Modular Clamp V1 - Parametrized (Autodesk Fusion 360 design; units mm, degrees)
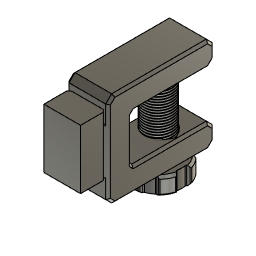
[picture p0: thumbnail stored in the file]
parameter "Thread_Diameter" = 25
parameter "Bolt_Head_Diameter" = 45
parameter "Bolt_Head_Height" = 15
parameter "Clamp_Clearance" = 40
parameter "Clamp_Strenght" = 20
parameter "Clamp_Length" = 70
parameter "Clamp_Thread_Clearance" = 10
parameter "Bolt_Length" = 60 (= "Clamp_Clearance + Clamp_Strenght")
parameter "Thread_Back_Offset" = 30 (= "Clamp_Strenght * 1.5")
parameter "Clamp_Width" = 35 (= "Thread_Diameter + Clamp_Strenght / 2")
parameter "Chamfer_Small" = 2 (= "Clamp_Strenght / 10")
parameter "Chamfer_Large" = 5 (= "Clamp_Strenght / 4")
parameter "Bolt_Chamfer" = 3.125 (= "Thread_Diameter / 8")
parameter "Thread_Tolerance_Additional" = 0.3
parameter "Knurling_Depth" = 3 (= "Bolt_Head_Diameter / 15")
parameter "Knurling_Angle" = 40
parameter "Mount_Strength" = 30
parameter "Mount_Height" = 40 (= "Clamp_Clearance")
parameter "Slot_Undercut" = 8
parameter "Slot_Height" = 20
parameter "Slot_Width" = 30
parameter "Mount_Chamfer_Tolerance" = 1
parameter "Slot_Tolerance" = 0.3
parameter "d157" = 15.5 (= "( Clamp_Width - Chamfer_Small * 2 ) / 2")
sketch "Clamp Side" plane through (0, 0, 0) normal (1, 0, 0) x axis (0, 1, 0)
  line L1 (-35, -20) -> (35, -20)
  line L2 (-35, 20) -> (-35, -20)
  line L3 (35, 20) -> (-35, 20)
  line L4 (35, -20) -> (35, 20)
  line L5 (-35, 20) -> (35, -20)
  line L6 (35, 20) -> (-35, -20)
  line L7 (-55, -40) -> (55, -40)
  line L8 (-55, 40) -> (-55, -40)
  line L9 (55, 40) -> (-55, 40)
  line L10 (55, -40) -> (55, 40)
  line L11 (49.6989, -40) -> (49.6989, 40)
  line L12 (-35, -60) -> (35, -60)
  line L13 (-35, 60) -> (-35, -60)
  line L14 (35, 60) -> (-35, 60)
  line L15 (35, -60) -> (35, 60)
  line L16 (-35, 60) -> (35, -60)
  line L17 (35, 60) -> (-35, -60)
  point P6 (0, 0)
  point P1 (0, 0)
  point P11 (49.6989, 40)
  point P12 (49.6989, -40)
  point P17 (0, 0)
  point P4 (-35, 20)
  point P5 (35, 20)
  point P3 (-35, -20)
  point P15 (-35, 60)
  point P16 (35, 60)
  point P14 (-35, -60)
  horizontal L1
  perpendicular L1 L2
  parallel L1 L3
  parallel L2 L4
  coincident L5 P6
  coincident L6 P6
  coincident P1 P6
  coincident L9 P11
  coincident L7 P12
  perpendicular L7 L11
  horizontal L12
  perpendicular L12 L13
  parallel L12 L14
  parallel L13 L15
  coincident L16 P17
  coincident L17 P17
  coincident P1 P17
  dimension "d8" distance P4 P5 = 70 (= "Clamp_Length")
  dimension "d9" distance P3 P4 = 40 (= "Clamp_Clearance")
  dimension "d21" distance P15 P16 = 70 (= "Clamp_Length")
  dimension "d22" distance P14 P15 = 120 (= "Bolt_Length + Clamp_Strenght * 3")
extrude "Extrude1" new body sketch "Clamp Side" profile of L1 L2 L3 L8 L7 L9 L12 L13 L14 L15 distance 17.5 (= "Clamp_Width / 2")
sketch "Thread and Bolt" plane through (0, 0, -40) normal (0, 0, -1) x axis (1, 0, 0)
  line L1 (17.5, 55) -> (17.5, -35)
  line L2 (-17.5, 55) -> (17.5, 55)
  line L3 (-17.5, -35) -> (-17.5, 55)
  line L4 (17.5, -35) -> (-17.5, -35)
  line L5 (19.5, -5) -> (22.5, -5)
  line L6 (19.0853, -1) -> (19.5, -5)
  line L7 (21.644, 1.147) -> (19.0853, -1)
  line L8 (15.0111, -5) -> (11.2583, 1.5)
  line L9 (19.5, -5) -> (0, -5)
  line L10 (11.2583, -5) -> (0, -5)
  line L11 (1.5, 1.5) -> (11.2583, 1.5)
  line L12 (1.5, -5) -> (1.5, 1.5)
  line L13 (11.2583, -5) -> (1.5, -5)
  line L14 (11.2583, 1.5) -> (11.2583, -5)
  line L15 (15.0111, -5) -> (11.2583, -11.5)
  line L16 (11.2583, -11.5) -> (11.2583, -5)
  line L17 (1.5, -11.5) -> (11.2583, -11.5)
  line L18 (1.5, -5) -> (1.5, -11.5)
  line L19 (5.9587, 43.003) -> (-11.5413, 43.003)
  line L20 (5.9587, 38.003) -> (5.9587, 43.003)
  line L21 (-11.5413, 38.003) -> (5.9587, 38.003)
  line L22 (-12.0413, 42.503) -> (-12.0413, 38.503)
  line L23 (2.4946, 35.3691) -> (2.4946, 45.637)
  line L24 (12.1369, 40.07) -> (3.2446, 34.936)
  line L25 (3.2446, 46.07) -> (12.1369, 40.936)
  circle C1 centre (0, -5) radius 12.5
  circle C2 centre (0, -5) radius 22.5
  circle C3 centre (0, -5) radius 9.375
  circle C4 centre (0, -5) radius 19.5
  circle C5 centre (0, -5) radius 13
  arc A1 centre (2.9946, 45.637) radius 0.5 clockwise from (2.4946, 45.637) to (3.2446, 46.07)
  arc A2 centre (11.8869, 40.503) radius 0.5 clockwise from (12.1369, 40.936) to (12.1369, 40.07)
  arc A3 centre (2.9946, 35.3691) radius 0.5 clockwise from (3.2446, 34.936) to (2.4946, 35.3691)
  arc A4 centre (-11.5413, 42.503) radius 0.5 clockwise from (-12.0413, 42.503) to (-11.5413, 43.003)
  arc A5 centre (-11.5413, 38.503) radius 0.5 clockwise from (-11.5413, 38.003) to (-12.0413, 38.503)
  point P6 (0, -5)
  point P7 (0, -5)
  point P11 (22.5, -5)
  point P12 (19.5, -5)
  point P13 (19.0853, -1)
  point P14 (21.644, 1.147)
  point P8 (0, -5)
  point P16 (0, -5)
  point P15 (15.0111, -5)
  point P17 (0, -5)
  point P20 (11.2583, 1.5)
  point P21 (11.2583, 1.5)
  point P26 (15.0111, -5)
  point P25 (11.2583, -11.5)
  point P28 (11.2583, -11.5)
  point P22 (1.5, 1.5)
  point P29 (1.5, -11.5)
  point P23 (1.5, -5)
  point P30 (1.5, -5)
  point P24 (11.2583, -5)
  point P27 (11.2583, -5)
  point P35 (5.9587, 40.503)
  point P33 (2.4946, 46.503)
  point P34 (2.4946, 34.503)
  point P9 (0, -5)
  coincident P6 P7
  concentric C1 C2
  concentric C2 C3
  coincident C2 P11
  coincident C4 P12
  perpendicular L1 L5
  coincident C4 P13
  coincident C2 P14
  coincident P8 L5
  coincident P8 P16
  coincident P15 L9
  horizontal L10
  coincident P6 P17
  tangent L8 C5
  horizontal L11
  vertical L12
  horizontal L13
  vertical L14
  collinear L9 L13
  coincident P20 P21
  symmetric P15 L9 P26
  symmetric L9 P20 P25
  symmetric L9 P21 P28
  symmetric L9 P22 P29
  symmetric L9 P23 P30
  symmetric L9 P24 P27
  horizontal L19
  vertical L20
  horizontal L21
  vertical L22
  parallel L22 L23
  midpoint L20 P35
  coincident P33 L23
  coincident P33 L25
  tangent L23 A1
  tangent L25 A1
  tangent L24 A2
  tangent L25 A2
  equal A1 A2
  coincident P34 L23
  coincident P34 L24
  tangent L23 A3
  tangent L24 A3
  equal A1 A3
  tangent L19 A4
  tangent L22 A4
  equal A1 A4
  tangent L21 A5
  tangent L22 A5
  equal A1 A5
  dimension "d17" diameter C1 = 25 (= "Thread_Diameter")
  dimension "d23" distance P7 L4 = 30 (= "Thread_Back_Offset")
  dimension "d26" diameter C2 = 45 (= "Bolt_Head_Diameter")
  dimension "d48" diameter C3 = 18.75 (= "Thread_Diameter - Bolt_Chamfer * 2")
  dimension "d55" distance L3 P9 = 17.5 (= "Clamp_Width / 2")
  dimension "d58" angle L5 L7 = 40 (= "Knurling_Angle")
  dimension "d73" angle L8 L9 = 60
  dimension "d80" = 0.5
  dimension "d81" distance P33 P34 = 12
  dimension "d82" radius A1 = 0.5
  dimension "d83" distance L19 L21 = 5
  dimension "d84" distance P33 P35 = 6 (= "d81 / 2")
  dimension "d182" distance P12 P13 = 4
extrude "Extrude2" cut sketch "Thread and Bolt" profile of C1 C3 to an object
thread "Thread1"
extrude "Extrude3" new body sketch "Thread and Bolt" profile of L1 L3 C1 C2 along normal blind 15 (= "Bolt_Head_Height") bodies "Bolt 60 mm"
extrude "Extrude4" new body sketch "Thread and Bolt" profile of C1 no distance stored
combine "Combine1"
chamfer "Chamfer3" distance 2 (= "Chamfer_Small")
thread "Thread2"
offset_faces "OffsetFaces4"
offset_faces "OffsetFaces5"
extrude "Extrude5" new body sketch "Thread and Bolt" profile of C1 C3 no distance stored
chamfer "Chamfer4" distance 3.125 (= "Bolt_Chamfer")
combine "Combine2"
chamfer "Chamfer5" distance 5 (= "Chamfer_Large")
chamfer "Chamfer6" distance 2 (= "Chamfer_Small")
chamfer "Chamfer7" distance 2 (= "Chamfer_Small")
extrude "Extrude6" cut sketch "Thread and Bolt" profile of L1 C2 C4 L5 L7 along normal blind 15 (= "Bolt_Head_Height")
mirror "Mirror1" mirrorStitchTolerance 0.1
fillet "Fillet2" radius 1 (= "Knurling_Depth / 3")
circular_pattern "C-Pattern2" TotalAngle 360
extrude "Extrude7" cut sketch "Thread and Bolt" profile of C1 C3 L8 L9 L10 C5 L11 L13 L14 L15 L16 L17 to an object
sketch "Mount Base" plane through (0, 0, 0) normal (0, 1, 0) x axis (1, 0, 0)
  line L1 (-15.5, 20) -> (15.5, 20)
  line L2 (-15.5, -20) -> (-15.5, 20)
  line L3 (15.5, -20) -> (-15.5, -20)
  line L4 (15.5, 20) -> (15.5, -20)
  line L5 (-15.5, -20) -> (15.5, 20)
  line L6 (15.5, -20) -> (-15.5, 20)
  point P6 (0, 0)
  point P1 (0, 0)
  point P4 (-15.5, -20)
  point P5 (15.5, -20)
  point P3 (-15.5, 20)
  horizontal L1
  perpendicular L1 L2
  parallel L1 L3
  parallel L2 L4
  coincident L5 P6
  coincident L6 P6
  coincident P1 P6
  dimension "d107" distance P4 P5 = 31
  dimension "d108" distance P3 P4 = 40
extrude "Extrude12" sketch "Mount Base" profile of L1 L2 L3 L4 no distance stored
sketch "Mount Profile" plane through (0, 0, -20) normal (0, 0, -1) x axis (1, 0, 0)
  line L1 (0, -22.5) -> (0, -1.75)
  line L2 (15.5, 55) -> (-15.5, 55)
  line L3 (15.5, 85) -> (15.5, 55)
  line L4 (-15.5, 85) -> (15.5, 85)
  line L5 (-15.5, 55) -> (-15.5, 85)
  line L6 (0, 55) -> (0, 85)
  line L7 (-2.1213, 68.3787) -> (-15.5, 55)
  line L8 (5.3866, 55) -> (-15.5, 55)
  line L9 (15.5, 55) -> (2.1213, 68.3787)
  line L10 (15.5, 55) -> (-15.5, 55)
  line L11 (-2.1213, 62.7218) -> (-9.8431, 55)
  line L12 (9.8431, 55) -> (2.1213, 62.7218)
  line L13 (-1.9092, 62.5097) -> (-9.631, 54.7879)
  line L14 (9.631, 54.7879) -> (1.9092, 62.5097)
  line L15 (15.5, 55) -> (-15.5, 55)
  line L16 (15.5, 76.2574) -> (15.5, 55)
  line L17 (-15.5, 76.2574) -> (15.5, 76.2574)
  line L18 (-15.5, 55) -> (-15.5, 76.2574)
  line L19 (12.6716, 52.1716) -> (9.8431, 55)
  line L20 (-12.6716, 52.1716) -> (12.6716, 52.1716)
  line L21 (-9.8431, 55) -> (-12.6716, 52.1716)
  line L22 (17.5, 53) -> (17.5, 49.1716)
  line L23 (15.5, 55) -> (12.6716, 52.1716)
  arc A1 centre (0, 66.2574) radius 3 clockwise from (-2.1213, 68.3787) to (2.1213, 68.3787)
  arc A2 centre (0, 60.6005) radius 3 clockwise from (-2.1213, 62.7218) to (2.1213, 62.7218)
  arc A3 centre (0, 60.6005) radius 2.7 clockwise from (-1.9092, 62.5097) to (1.9092, 62.5097)
  point P8 (0, 85)
  point P9 (0, 55)
  point P4 (-15.5, 55)
  point P10 (-15.5, 55)
  point P5 (15.5, 55)
  point P12 (15.5, 55)
  point P13 (-9.8431, 55)
  point P14 (9.8431, 55)
  point P28 (15.5, 76.2574)
  point P26 (-15.5, 55)
  point P17 (0, 66.2574)
  point P34 (15.5, 55)
  midpoint L4 P8
  midpoint L2 P9
  horizontal L8
  coincident P4 P10
  coincident P5 P12
  coincident L8 P13
  parallel L7 L11
  coincident L2 P14
  parallel L9 L12
  tangent L7 A1
  tangent L9 A1
  tangent L12 A2
  tangent L11 A2
  equal A1 A2
  horizontal L15
  vertical L16
  horizontal L17
  vertical L18
  coincident L3 P28
  coincident P4 P26
  parallel L9 L19
  parallel L15 L20
  parallel L11 L21
  coincident L6 P17
  coincident P5 P34
  dimension "d159" angle L7 L8 = 45
  dimension "d160" distance L7 L11 = 4
  dimension "d162" radius A1 = 3
  dimension "d166" distance P17 L17 = 10
  dimension "d172" distance L9 L12 = 4 (= "d160")
  dimension "d179" angle L20 L23 = 45
extrude "Extrude17" cut sketch "Mount Profile" profile of L2 L3 L4 L5 L6 L7 L9 L10 L11 L12 no distance stored
chamfer "Chamfer16" distance 0.5 distance 10
extrude "Extrude18" new body sketch "Mount Profile" profile of L2 L3 L5 L6 L7 L9 L10 A1 L13 A3 L14 L15 L16 L17 L18 to an object bodies "Modular Mount Block Template"
extrude "Extrude19" sketch "Mount Profile" profile of L2 L3 L5 L6 L7 L9 L10 L11 L12 A1 A2 L13 A3 L14 L15 L16 L17 L18 blind -10
combine "Combine4"
chamfer "Chamfer17" distance 2
chamfer "Chamfer18" distance 2 (= "Chamfer_Small")
chamfer "Chamfer19" distance 1
chamfer "Chamfer20" distance 1
chamfer "Chamfer21" distance 1
chamfer "Chamfer22" distance 1
chamfer "Chamfer23" distance 1
named bodies: "Modular Clamp 40 mm", "Bolt 60 mm", "Modular Mount Block Template"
